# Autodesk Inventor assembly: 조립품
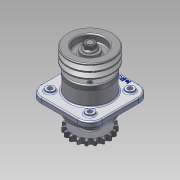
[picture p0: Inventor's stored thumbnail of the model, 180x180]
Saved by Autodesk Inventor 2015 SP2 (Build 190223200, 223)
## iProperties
Created: 2015-07
Part Number: 조립품
Document SubType Name: Assembly
Designer: AMC
Author: AMC
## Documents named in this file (11)
- C:\Users\AMC\Desktop\450735V1014\조립품.iam
- C:\Users\AMC\Desktop\450735V1014\본체.ipt
- C:\Users\AMC\Desktop\450735V1014\6-베어링 6206.ipt
- C:\Users\AMC\Desktop\450735V1014\2-커버.ipt
- C:\Users\AMC\Desktop\450735V1014\3-축.ipt
- C:\Users\AMC\Desktop\450735V1014\7-부시.ipt
- C:\Users\AMC\Desktop\450735V1014\10-M6.ipt
- C:\Users\AMC\Desktop\450735V1014\11-키 6x6.ipt
- C:\Users\AMC\Desktop\450735V1014\4-V벨트풀리.ipt
- C:\Users\AMC\Desktop\450735V1014\5-체인 스프로킷.ipt
- C:\Users\AMC\Desktop\450735V1014\9-M16-너트.ipt
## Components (20 placed, 9 different names)
1. 6-베어링 6206:1
2. 6-베어링 6206:2
3. 2-커버:1
4. 2-커버:2
5. 3-축:1
6. 7-부시:1
7. 11-키 6x6:1 — 각도:1
8. 11-키 6x6:2 — 각도:2
9. 4-V벨트풀리:1 — 각도:1
10. 5-체인 스프로킷:1 — 각도:2
11. 9-M16 너트:1
12. 9-M16 너트:2
13. 10-M6:2
14. 10-M6:3
15. 10-M6:4
16. 10-M6:5
17. 10-M6:1
18. 10-M6:6
19. 10-M6:7
20. 10-M6:8
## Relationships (2: Angle 2)
- 각도:1 [Angle]: 11-키 6x6:1 ↔ 4-V벨트풀리:1
- 각도:2 [Angle]: 11-키 6x6:2 ↔ 5-체인 스프로킷:1
